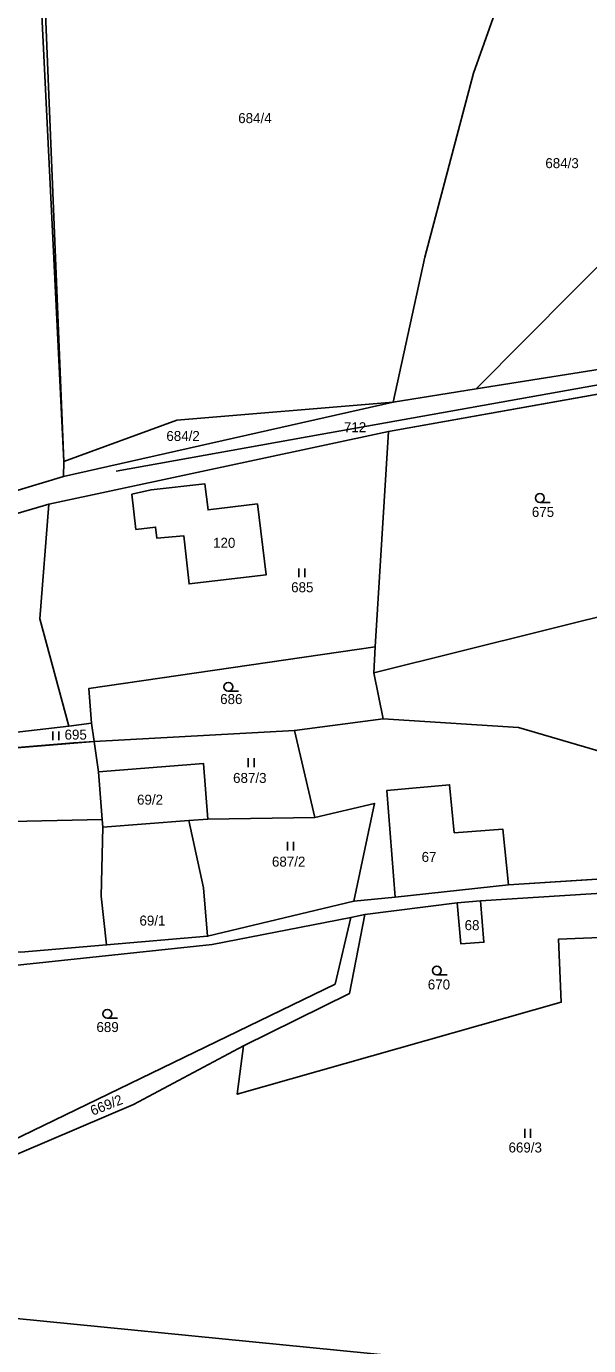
# Model space of a CAD drawing. Extents: x -590606 to -587796, y -1065936 to -1062515.
# Drawn here: x -589814.6 to -589718.9, y -1064760.8 to -1064536.2 of the extents above; entities that cross this region are included whole.
import ezdxf

# ---------------------------------------------------------------- set-up
doc = ezdxf.new("R2010")
doc.units = 0
for name, color, linetype in [('Cesty', 7, 'Continuous'), ('Parcela nároku', 7, 'Continuous'), ('Vnější obvod_ Studené', 7, 'Continuous'), ('Vrstva 30', 7, 'Continuous'), ('Územní plán', 7, 'Continuous')]:
    doc.layers.add(name, color=color, linetype=linetype)

msp = doc.modelspace()

# ---------------------------------------------------------------- linework, layer by layer
at = {"layer": 'Cesty'}
msp.add_lwpolyline([(-589312.39, -1064575.92), (-589318.72, -1064584.83), (-589335.76, -1064596.6), (-589354.95, -1064613.9), (-589370.21, -1064620.11), (-589392.14, -1064624.65), (-589405.6, -1064625.31), (-589467.35, -1064625.2), (-589485.5, -1064624.04), (-589517.23, -1064616.87), (-589543.56, -1064607.17), (-589549.94, -1064607.84), (-589566.34, -1064608.24), (-589595.98, -1064606.38), (-589632.73, -1064602.69), (-589650.77, -1064600.08), (-589699.72, -1064596.26), (-589711.59, -1064596.2), (-589764.62, -1064605.69), (-589799.36, -1064611.91)], dxfattribs=at)
at = {"layer": 'Parcela nároku'}
for points in [[(-589813.71, -1064476.97), (-589812.63, -1064521.48), (-589808.25, -1064610.3), (-589808.34, -1064612.83), (-589850.56, -1064625.55), (-589859.55, -1064532.21), (-589866.7, -1064505.87), (-589870.68, -1064462.95), (-589869.39, -1064418.76), (-589851.16, -1064443.43), (-589836.69, -1064459.05), (-589820.49, -1064473.59)], [(-589803.68, -1064480.89), (-589763.64, -1064487.8), (-589734.97, -1064501.33), (-589725.8, -1064508.32), (-589738.54, -1064544.17), (-589746.83, -1064575.48), (-589752.19, -1064600.19), (-589789.05, -1064603.26), (-589808.25, -1064610.3), (-589812.63, -1064521.48), (-589813.71, -1064476.97)], [(-589725.8, -1064508.32), (-589706.11, -1064524.65), (-589680.03, -1064539.44), (-589738.08, -1064597.9), (-589752.19, -1064600.19), (-589746.83, -1064575.48), (-589738.54, -1064544.17)], [(-589680.03, -1064539.44), (-589738.08, -1064597.9), (-589710.88, -1064593.56), (-589696.02, -1064593.97), (-589648.45, -1064550.62), (-589665.91, -1064545.7)], [(-589755.28, -1064641.85), (-589755.52, -1064646.24), (-589711.55, -1064635.28), (-589709.54, -1064625.13), (-589692.09, -1064629.64), (-589684.98, -1064622.56), (-589710.09, -1064597.48), (-589753, -1064605.14)], [(-589789.05, -1064603.26), (-589752.19, -1064600.19), (-589808.34, -1064612.83), (-589808.25, -1064610.3)], [(-589810.83, -1064617.52), (-589753, -1064605.14), (-589755.28, -1064641.85), (-589804.02, -1064648.95), (-589803.58, -1064654.81), (-589807.43, -1064655.35), (-589812.35, -1064637.06)], [(-589784.24, -1064614.1), (-589783.72, -1064618.52), (-589775.31, -1064617.51), (-589773.83, -1064629.6), (-589786.95, -1064631.12), (-589787.84, -1064622.93), (-589792.42, -1064623.33), (-589792.65, -1064621.45), (-589796, -1064621.83), (-589796.67, -1064615.84), (-589793.42, -1064615.08)], [(-589773.83, -1064629.6), (-589786.95, -1064631.12), (-589787.84, -1064622.93), (-589792.42, -1064623.33), (-589792.65, -1064621.45), (-589796, -1064621.83), (-589796.67, -1064615.84), (-589793.42, -1064615.08), (-589784.24, -1064614.1), (-589783.72, -1064618.52), (-589775.31, -1064617.51)], [(-589812.35, -1064637.06), (-589807.43, -1064655.35), (-589854.05, -1064660.75), (-589850.49, -1064629.2), (-589810.83, -1064617.52)], [(-589711.55, -1064635.28), (-589667.65, -1064653.64), (-589674.51, -1064672.1), (-589730.86, -1064655.58), (-589753.92, -1064654.08), (-589755.52, -1064646.24)], [(-589753.92, -1064654.08), (-589755.52, -1064646.24), (-589755.28, -1064641.85), (-589804.02, -1064648.95), (-589803.58, -1064654.81), (-589803.11, -1064657.97), (-589769.01, -1064656.08)], [(-589807.43, -1064655.35), (-589854.05, -1064660.75), (-589854.21, -1064662.15), (-589806.62, -1064658.16), (-589803.11, -1064657.97), (-589803.58, -1064654.81)], [(-589753.3, -1064666.31), (-589751.87, -1064684.47), (-589758.89, -1064685.17), (-589755.37, -1064668.5), (-589765.53, -1064670.88), (-589769.01, -1064656.08), (-589753.92, -1064654.08), (-589730.86, -1064655.58), (-589674.51, -1064672.1), (-589658.93, -1064681.99), (-589653.5, -1064688.41), (-589638.89, -1064692.66), (-589640.04, -1064694.73), (-589662.7, -1064687.77), (-589676.27, -1064682.49), (-589698.92, -1064680.19), (-589732.55, -1064682.34), (-589733.53, -1064672.91), (-589741.81, -1064673.48), (-589742.61, -1064665.31)], [(-589769.01, -1064656.08), (-589765.53, -1064670.88), (-589783.74, -1064671.16), (-589784.51, -1064661.7), (-589802.35, -1064663.1), (-589803.11, -1064657.97)], [(-589855.58, -1064672.44), (-589854.21, -1064662.15), (-589806.62, -1064658.16), (-589803.11, -1064657.97), (-589802.35, -1064663.1), (-589801.71, -1064671.23)], [(-589802.35, -1064663.1), (-589784.51, -1064661.7), (-589783.74, -1064671.16), (-589786.97, -1064671.41), (-589801.6, -1064672.57), (-589801.71, -1064671.23)], [(-589732.55, -1064682.34), (-589733.53, -1064672.91), (-589741.81, -1064673.48), (-589742.61, -1064665.31), (-589753.3, -1064666.31), (-589751.87, -1064684.47)], [(-589755.37, -1064668.5), (-589765.53, -1064670.88), (-589783.74, -1064671.16), (-589786.97, -1064671.41), (-589784.5, -1064682.88), (-589783.78, -1064691.12), (-589758.89, -1064685.17)], [(-589801.89, -1064684.29), (-589800.98, -1064692.6), (-589815.56, -1064693.85), (-589845.68, -1064693.13), (-589860.43, -1064681.93), (-589855.58, -1064672.44), (-589801.71, -1064671.23), (-589801.6, -1064672.57)], [(-589786.97, -1064671.41), (-589801.6, -1064672.57), (-589801.89, -1064684.29), (-589800.98, -1064692.6), (-589783.78, -1064691.12), (-589784.5, -1064682.88)], [(-589740.69, -1064692.4), (-589736.77, -1064692.13), (-589737.33, -1064685.11), (-589698.77, -1064682.65), (-589676.81, -1064685.44), (-589642, -1064696.9), (-589650.2, -1064705.57), (-589680.26, -1064689.83), (-589724.05, -1064691.59), (-589723.58, -1064702.36), (-589778.73, -1064718.01), (-589777.67, -1064709.79), (-589759.62, -1064700.86), (-589757.03, -1064687.42), (-589741.31, -1064685.44)], [(-589737.33, -1064685.11), (-589741.31, -1064685.44), (-589740.69, -1064692.4), (-589736.77, -1064692.13)], [(-589759.39, -1064687.91), (-589783.04, -1064692.55), (-589817.72, -1064696.23), (-589869.78, -1064697.18), (-589865.85, -1064705.92), (-589818.62, -1064707.21), (-589817.25, -1064726.04), (-589762.08, -1064699.26)], [(-589762.08, -1064699.26), (-589817.25, -1064726.04), (-589850.49, -1064739.56), (-589868.03, -1064748.13), (-589866.87, -1064751.2), (-589844.17, -1064740.14), (-589796.41, -1064719.77), (-589777.67, -1064709.79), (-589759.62, -1064700.86), (-589757.03, -1064687.42), (-589759.39, -1064687.91)], [(-589680.26, -1064689.83), (-589650.2, -1064705.57), (-589660.64, -1064716.31), (-589690.55, -1064743.96), (-589713.8, -1064760.35), (-589721.04, -1064765.62), (-589866.87, -1064751.2), (-589844.17, -1064740.14), (-589796.41, -1064719.77), (-589777.67, -1064709.79), (-589778.73, -1064718.01), (-589723.58, -1064702.36), (-589724.05, -1064691.59)], [(-589879.87, -1064753.99), (-589868.03, -1064748.13), (-589866.87, -1064751.2), (-589721.04, -1064765.62), (-589732.48, -1064773.33), (-589781.14, -1064797.6), (-589848.05, -1064822.46), (-589965.99, -1064862.62), (-590008.01, -1064872.65), (-590021.45, -1064817.05), (-590021.33, -1064814.7), (-589976.81, -1064797.92), (-589940.65, -1064780.54)]]:
    msp.add_lwpolyline(points, close=True, dxfattribs=at)
for points in [[(-589850.56, -1064625.55), (-589808.34, -1064612.83), (-589752.19, -1064600.19), (-589738.08, -1064597.9), (-589710.88, -1064593.56), (-589696.02, -1064593.97), (-589645.99, -1064597.91), (-589599.74, -1064604.8), (-589596.03, -1064605.35), (-589549.09, -1064606.72), (-589546.05, -1064609.19), (-589552.79, -1064610.5), (-589564.95, -1064610.02), (-589586.36, -1064609.18), (-589594.13, -1064607.9), (-589600.62, -1064606.83), (-589651.05, -1064601), (-589706.94, -1064597.01), (-589710.09, -1064597.48), (-589753, -1064605.14), (-589810.83, -1064617.52), (-589850.49, -1064629.2)], [(-589588.45, -1064763.67), (-589590.38, -1064760.46), (-589599.12, -1064738.99), (-589613.14, -1064712.47), (-589608.96, -1064707.26), (-589627.55, -1064698.31), (-589640.04, -1064694.73), (-589662.7, -1064687.77), (-589676.27, -1064682.49), (-589698.92, -1064680.19), (-589732.55, -1064682.34), (-589751.87, -1064684.47), (-589758.89, -1064685.17), (-589783.78, -1064691.12), (-589800.98, -1064692.6), (-589815.56, -1064693.85)], [(-589817.72, -1064696.23), (-589783.04, -1064692.55), (-589759.39, -1064687.91), (-589757.03, -1064687.42), (-589741.31, -1064685.44), (-589737.33, -1064685.11), (-589698.77, -1064682.65), (-589676.81, -1064685.44), (-589642, -1064696.9), (-589630.34, -1064701.27), (-589615.6, -1064714.57), (-589618.13, -1064717.98), (-589605.54, -1064732.57), (-589597.63, -1064749.22), (-589593.02, -1064762.59)]]:
    msp.add_lwpolyline(points, dxfattribs=at)
at = {"layer": 'Vnější obvod_ Studené'}
for p, q in [((-589753, -1064605.14), (-589710.09, -1064597.48)), ((-589810.83, -1064617.52), (-589753, -1064605.14)), ((-589812.35, -1064637.06), (-589810.83, -1064617.52)), ((-589807.43, -1064655.35), (-589812.35, -1064637.06)), ((-589803.58, -1064654.81), (-589807.43, -1064655.35)), ((-589803.11, -1064657.97), (-589803.58, -1064654.81)), ((-589854.21, -1064662.15), (-589803.11, -1064657.97)), ((-589698.92, -1064680.19), (-589732.55, -1064682.34)), ((-589732.55, -1064682.34), (-589751.87, -1064684.47)), ((-589758.89, -1064685.17), (-589783.78, -1064691.12)), ((-589751.87, -1064684.47), (-589758.89, -1064685.17)), ((-589800.98, -1064692.6), (-589815.56, -1064693.85)), ((-589783.78, -1064691.12), (-589800.98, -1064692.6))]:
    msp.add_line(p, q, dxfattribs=at)
at = {"layer": 'Vrstva 30'}
for p, q in [((-589725.48, -1064617.24), (-589727.23, -1064617.24)), ((-589768.25, -1064628.47), (-589768.25, -1064629.97)), ((-589767.22, -1064629.97), (-589767.22, -1064628.47)), ((-589778.51, -1064649.4), (-589780.26, -1064649.4)), ((-589810.14, -1064656.24), (-589810.14, -1064657.74)), ((-589809.11, -1064657.74), (-589809.11, -1064656.24)), ((-589776.88, -1064660.82), (-589776.88, -1064662.32)), ((-589775.85, -1064662.32), (-589775.85, -1064660.82)), ((-589770.17, -1064675.02), (-589770.17, -1064676.52)), ((-589769.15, -1064676.52), (-589769.15, -1064675.02)), ((-589743.03, -1064697.71), (-589744.78, -1064697.71)), ((-589799.11, -1064705.08), (-589800.86, -1064705.08)), ((-589729.82, -1064723.92), (-589729.82, -1064725.42)), ((-589728.8, -1064725.42), (-589728.8, -1064723.92))]:
    msp.add_line(p, q, dxfattribs=at)
for centre in [(-589727.23, -1064616.49), (-589780.26, -1064648.65), (-589744.78, -1064696.96), (-589800.86, -1064704.33)]:
    msp.add_circle(centre, 0.75, dxfattribs=at)
at = {"layer": 'Územní plán'}
msp.add_lwpolyline([(-589808.25, -1064610.3), (-589813.71, -1064476.97), (-589803.68, -1064480.89), (-589763.64, -1064487.8), (-589734.97, -1064501.33), (-589725.8, -1064508.32), (-589706.11, -1064524.65), (-589680.03, -1064539.44), (-589665.91, -1064545.7), (-589648.45, -1064550.62), (-589634.11, -1064554.06), (-589619.77, -1064557.49), (-589601.81, -1064568.51), (-589595.88, -1064573.42), (-589599.74, -1064604.8), (-589645.99, -1064597.91), (-589696.02, -1064593.97), (-589710.88, -1064593.56), (-589738.08, -1064597.9), (-589752.19, -1064600.19), (-589789.05, -1064603.26), (-589808.25, -1064610.3)], dxfattribs=at)

# ---------------------------------------------------------------- texts
at = {"layer": 'Parcela nároku'}
for s, p in [('684/4', (-589778.58, -1064552.65)), ('684/3', (-589726.3, -1064560.32)), ('684/2', (-589790.81, -1064606.78)), ('712', (-589760.59, -1064605.29)), ('675', (-589728.6, -1064619.71)), ('120', (-589782.86, -1064624.97)), ('685', (-589769.57, -1064632.54)), ('686', (-589781.65, -1064651.58)), ('695', (-589808.14, -1064657.63)), ('687/3', (-589779.45, -1064665.01)), ('69/2', (-589795.8, -1064668.71)), ('687/2', (-589772.84, -1064679.26)), ('67', (-589747.36, -1064678.46)), ('69/1', (-589795.39, -1064689.3)), ('68', (-589740.04, -1064690.08)), ('670', (-589746.31, -1064700.18)), ('689', (-589802.71, -1064707.43)), ('669/3', (-589732.57, -1064727.94))]:
    msp.add_text(s, height=1.7, dxfattribs=at).set_placement(p)
msp.add_text('669/2', height=1.7, rotation=21.6979, dxfattribs=at).set_placement((-589803.34, -1064721.7))

doc.saveas('drawing.dxf')
